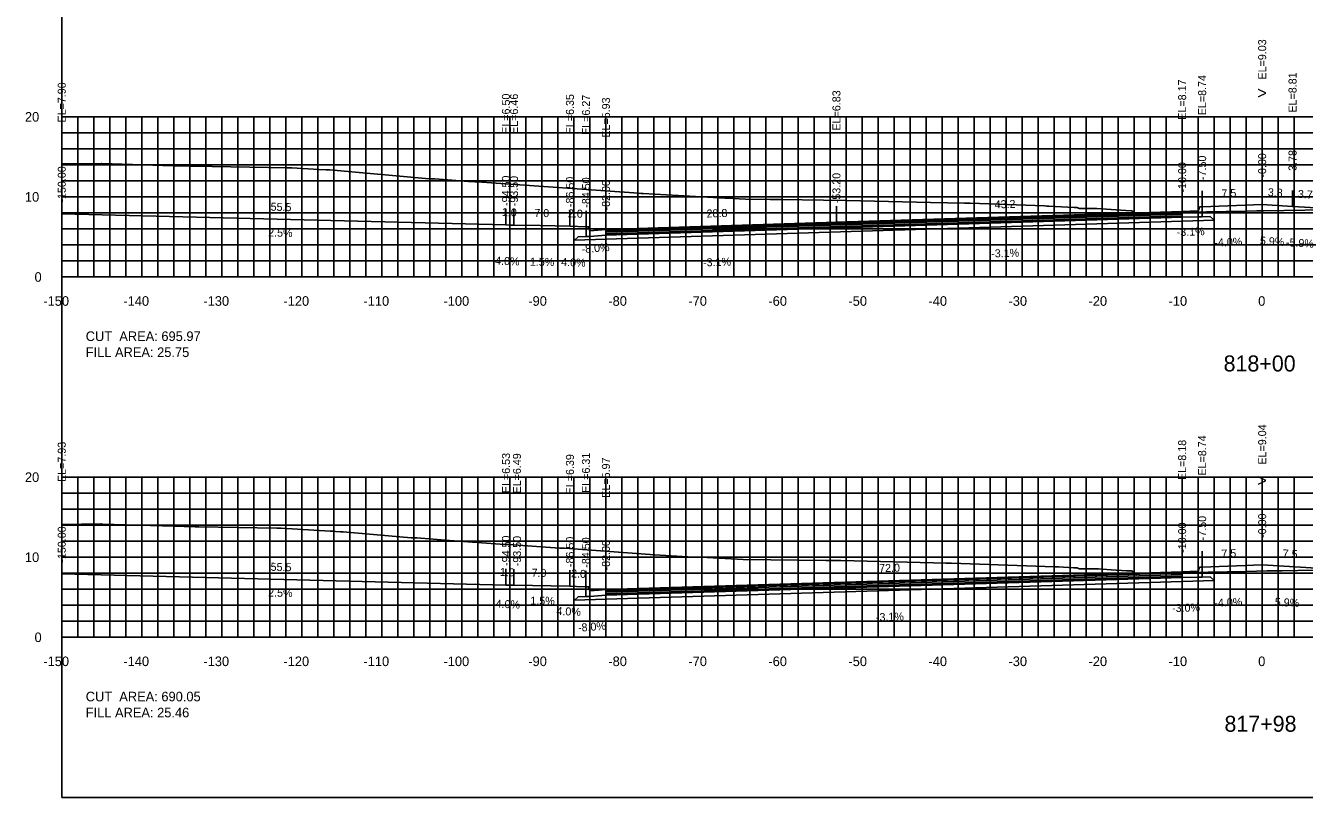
# Model space of a CAD drawing. Extents: x 1797419 to 1809236, y 248759 to 251512.
# Drawn here: x 1805536.5 to 1805696.3, y 250079.4 to 250175.8 of the extents above; entities that cross this region are included whole.
import ezdxf

# ---------------------------------------------------------------- set-up
doc = ezdxf.new("R2010")
doc.units = 0
for name, color, linetype in [('1', 7, 'Continuous'), ('10', 7, 'Continuous'), ('3', 7, 'Continuous'), ('31', 7, 'Continuous'), ('4', 7, 'Continuous'), ('60', 7, 'Continuous'), ('ANNO-TXT', 7, 'Continuous'), ('BASE', 7, 'Continuous'), ('CL-CNST', 7, 'Continuous'), ('Level 62', 7, 'Continuous'), ('LOWER BINDER', 7, 'Continuous'), ('M-ROADS', 7, 'Continuous'), ('UPPER BINDER', 7, 'Continuous'), ('WEARING', 7, 'Continuous')]:
    doc.layers.add(name, color=color, linetype=linetype)

msp = doc.modelspace()

# ---------------------------------------------------------------- linework, layer by layer
for p, q in [((1805691, 250153.47), (1805691, 250155.47)), ((1805541, 250152.33), (1805541, 250154.33)), ((1805681, 250152.6), (1805681, 250154.6)), ((1805683.5, 250153.17), (1805683.5, 250155.17)), ((1805694.79, 250153.24), (1805694.79, 250155.24)), ((1805596.5, 250150.93), (1805596.5, 250152.93)), ((1805597.51, 250150.89), (1805597.51, 250152.89)), ((1805604.5, 250150.78), (1805604.5, 250152.78)), ((1805606.51, 250150.7), (1805606.51, 250152.7)), ((1805609, 250150.36), (1805609, 250152.36)), ((1805637.8, 250151.26), (1805637.8, 250153.26)), ((1805541, 250107.36), (1805541, 250109.36)), ((1805681, 250107.61), (1805681, 250109.61)), ((1805683.5, 250108.17), (1805683.5, 250110.17)), ((1805691, 250108.47), (1805691, 250110.47)), ((1805596.51, 250105.96), (1805596.51, 250107.96)), ((1805597.51, 250105.92), (1805597.51, 250107.92)), ((1805604.5, 250105.82), (1805604.5, 250107.82)), ((1805606.5, 250105.74), (1805606.5, 250107.74)), ((1805609, 250105.4), (1805609, 250107.4))]:
    msp.add_line(p, q)
for points in [[(1805541, 250079.43), (1805841, 250079.43), (1805841, 250269.43), (1805541, 250269.43)], [(1805683.5, 250153.17), (1805683.17, 250153.17), (1805683, 250152.67), (1805681, 250152.6), (1805681, 250151.88), (1805683, 250151.95), (1805683.5, 250151.95)], [(1805609, 250150.36), (1805607, 250150.2), (1805606.83, 250150.7), (1805606.51, 250150.7), (1805606.51, 250149.48), (1805607, 250149.48), (1805609, 250149.64)], [(1805683.5, 250108.17), (1805683.17, 250108.17), (1805683, 250107.67), (1805681, 250107.61), (1805681, 250106.89), (1805683, 250106.95), (1805683.5, 250106.95)], [(1805609, 250105.4), (1805607, 250105.24), (1805606.83, 250105.74), (1805606.5, 250105.74), (1805606.5, 250104.52), (1805607, 250104.52), (1805609, 250104.68)]]:
    msp.add_lwpolyline(points, close=True)
at = {"layer": '60'}
for p, q in [((1805540.94, 250164.43), (1805541, 250164.43)), ((1805541, 250144.43), (1805541, 250164.43)), ((1805540.94, 250154.43), (1805541, 250154.43)), ((1805540.94, 250144.43), (1805541, 250144.43)), ((1805541, 250144.43), (1805841, 250144.43)), ((1805541, 250144.37), (1805541, 250144.43)), ((1805551, 250144.37), (1805551, 250144.43)), ((1805561, 250144.37), (1805561, 250144.43)), ((1805571, 250144.37), (1805571, 250144.43)), ((1805581, 250144.37), (1805581, 250144.43)), ((1805591, 250144.37), (1805591, 250144.43)), ((1805601, 250144.37), (1805601, 250144.43)), ((1805611, 250144.37), (1805611, 250144.43)), ((1805621, 250144.37), (1805621, 250144.43)), ((1805631, 250144.37), (1805631, 250144.43)), ((1805641, 250144.37), (1805641, 250144.43)), ((1805651, 250144.37), (1805651, 250144.43)), ((1805661, 250144.37), (1805661, 250144.43)), ((1805671, 250144.37), (1805671, 250144.43)), ((1805681, 250144.37), (1805681, 250144.43)), ((1805691, 250144.37), (1805691, 250144.43)), ((1805540.94, 250119.43), (1805541, 250119.43)), ((1805541, 250099.43), (1805541, 250119.43)), ((1805540.94, 250109.43), (1805541, 250109.43)), ((1805540.94, 250099.43), (1805541, 250099.43)), ((1805541, 250099.43), (1805841, 250099.43)), ((1805541, 250099.37), (1805541, 250099.43)), ((1805551, 250099.37), (1805551, 250099.43)), ((1805561, 250099.37), (1805561, 250099.43)), ((1805571, 250099.37), (1805571, 250099.43)), ((1805581, 250099.37), (1805581, 250099.43)), ((1805591, 250099.37), (1805591, 250099.43)), ((1805601, 250099.37), (1805601, 250099.43)), ((1805611, 250099.37), (1805611, 250099.43)), ((1805621, 250099.37), (1805621, 250099.43)), ((1805631, 250099.37), (1805631, 250099.43)), ((1805641, 250099.37), (1805641, 250099.43)), ((1805651, 250099.37), (1805651, 250099.43)), ((1805661, 250099.37), (1805661, 250099.43)), ((1805671, 250099.37), (1805671, 250099.43)), ((1805681, 250099.37), (1805681, 250099.43)), ((1805691, 250099.37), (1805691, 250099.43))]:
    msp.add_line(p, q, dxfattribs=at)
at = {"layer": 'BASE'}
for points in [[(1805605.06, 250149.02), (1805605.51, 250149.46), (1805606.51, 250149.48), (1805607, 250149.48), (1805609, 250149.64), (1805681, 250151.88), (1805683, 250151.95), (1805683.5, 250151.95), (1805684.5, 250151.98), (1805684.98, 250151.51), (1805681, 250151.38), (1805609, 250149.14)], [(1805605.07, 250104.06), (1805605.51, 250104.5), (1805606.5, 250104.52), (1805607, 250104.52), (1805609, 250104.68), (1805681, 250106.89), (1805683, 250106.95), (1805683.5, 250106.95), (1805684.5, 250106.98), (1805684.98, 250106.51), (1805681, 250106.39), (1805609, 250104.18)]]:
    msp.add_lwpolyline(points, close=True, dxfattribs=at)
at = {"layer": 'CL-CNST'}
for points in [[(1805541, 250152.33), (1805596.5, 250150.93), (1805597, 250150.91), (1805597.51, 250150.89), (1805600.8, 250150.84), (1805604.5, 250150.78), (1805606.51, 250150.7), (1805606.71, 250150.7), (1805606.83, 250150.7), (1805606.9, 250150.51), (1805607, 250150.2), (1805609, 250150.36), (1805637.8, 250151.26), (1805681, 250152.6), (1805683, 250152.67), (1805683.11, 250152.99), (1805683.17, 250153.17), (1805683.38, 250153.17), (1805683.5, 250153.17), (1805691, 250153.47), (1805694.79, 250153.24), (1805698.5, 250153.02)], [(1805541, 250107.36), (1805596.51, 250105.96), (1805597.51, 250105.92), (1805604.5, 250105.82), (1805605.32, 250105.79), (1805606.5, 250105.74), (1805606.63, 250105.74), (1805606.83, 250105.74), (1805607, 250105.24), (1805608.1, 250105.33), (1805609, 250105.4), (1805681, 250107.61), (1805683, 250107.67), (1805683.17, 250108.17), (1805683.5, 250108.17), (1805691, 250108.47), (1805698.5, 250108.03)]]:
    msp.add_lwpolyline(points, dxfattribs=at)
at = {"layer": 'Level 62'}
for p, q in [((1805541, 250164.43), (1805841, 250164.43)), ((1805541, 250144.43), (1805541, 250164.43)), ((1805543, 250144.43), (1805543, 250164.43)), ((1805545, 250144.43), (1805545, 250164.43)), ((1805547, 250144.43), (1805547, 250164.43)), ((1805549, 250144.43), (1805549, 250164.43)), ((1805551, 250144.43), (1805551, 250164.43)), ((1805553, 250144.43), (1805553, 250164.43)), ((1805555, 250144.43), (1805555, 250164.43)), ((1805557, 250144.43), (1805557, 250164.43)), ((1805559, 250144.43), (1805559, 250164.43)), ((1805561, 250144.43), (1805561, 250164.43)), ((1805563, 250144.43), (1805563, 250164.43)), ((1805565, 250144.43), (1805565, 250164.43)), ((1805567, 250144.43), (1805567, 250164.43)), ((1805569, 250144.43), (1805569, 250164.43)), ((1805571, 250144.43), (1805571, 250164.43)), ((1805573, 250144.43), (1805573, 250164.43)), ((1805575, 250144.43), (1805575, 250164.43)), ((1805577, 250144.43), (1805577, 250164.43)), ((1805579, 250144.43), (1805579, 250164.43)), ((1805581, 250144.43), (1805581, 250164.43)), ((1805583, 250144.43), (1805583, 250164.43)), ((1805585, 250144.43), (1805585, 250164.43)), ((1805587, 250144.43), (1805587, 250164.43)), ((1805589, 250144.43), (1805589, 250164.43)), ((1805591, 250144.43), (1805591, 250164.43)), ((1805593, 250144.43), (1805593, 250164.43)), ((1805595, 250144.43), (1805595, 250164.43)), ((1805597, 250144.43), (1805597, 250164.43)), ((1805599, 250144.43), (1805599, 250164.43)), ((1805601, 250144.43), (1805601, 250164.43)), ((1805603, 250144.43), (1805603, 250164.43)), ((1805605, 250144.43), (1805605, 250164.43)), ((1805607, 250144.43), (1805607, 250164.43)), ((1805609, 250144.43), (1805609, 250164.43)), ((1805611, 250144.43), (1805611, 250164.43)), ((1805613, 250144.43), (1805613, 250164.43)), ((1805615, 250144.43), (1805615, 250164.43)), ((1805617, 250144.43), (1805617, 250164.43)), ((1805619, 250144.43), (1805619, 250164.43)), ((1805621, 250144.43), (1805621, 250164.43)), ((1805623, 250144.43), (1805623, 250164.43)), ((1805625, 250144.43), (1805625, 250164.43)), ((1805627, 250144.43), (1805627, 250164.43)), ((1805629, 250144.43), (1805629, 250164.43)), ((1805631, 250144.43), (1805631, 250164.43)), ((1805633, 250144.43), (1805633, 250164.43)), ((1805635, 250144.43), (1805635, 250164.43)), ((1805637, 250144.43), (1805637, 250164.43)), ((1805639, 250144.43), (1805639, 250164.43)), ((1805641, 250144.43), (1805641, 250164.43)), ((1805643, 250144.43), (1805643, 250164.43)), ((1805645, 250144.43), (1805645, 250164.43)), ((1805647, 250144.43), (1805647, 250164.43)), ((1805649, 250144.43), (1805649, 250164.43)), ((1805651, 250144.43), (1805651, 250164.43)), ((1805653, 250144.43), (1805653, 250164.43)), ((1805655, 250144.43), (1805655, 250164.43)), ((1805657, 250144.43), (1805657, 250164.43)), ((1805659, 250144.43), (1805659, 250164.43)), ((1805661, 250144.43), (1805661, 250164.43)), ((1805663, 250144.43), (1805663, 250164.43)), ((1805665, 250144.43), (1805665, 250164.43)), ((1805667, 250144.43), (1805667, 250164.43)), ((1805669, 250144.43), (1805669, 250164.43)), ((1805671, 250144.43), (1805671, 250164.43)), ((1805673, 250144.43), (1805673, 250164.43)), ((1805675, 250144.43), (1805675, 250164.43)), ((1805677, 250144.43), (1805677, 250164.43)), ((1805679, 250144.43), (1805679, 250164.43)), ((1805681, 250144.43), (1805681, 250164.43)), ((1805683, 250144.43), (1805683, 250164.43)), ((1805685, 250144.43), (1805685, 250164.43)), ((1805687, 250144.43), (1805687, 250164.43)), ((1805689, 250144.43), (1805689, 250164.43)), ((1805691, 250144.43), (1805691, 250164.43)), ((1805693, 250144.43), (1805693, 250164.43)), ((1805695, 250144.43), (1805695, 250164.43)), ((1805541, 250162.43), (1805841, 250162.43)), ((1805541, 250160.43), (1805841, 250160.43)), ((1805541, 250158.43), (1805841, 250158.43)), ((1805541, 250156.43), (1805841, 250156.43)), ((1805541, 250154.43), (1805841, 250154.43)), ((1805541, 250152.43), (1805841, 250152.43)), ((1805541, 250150.43), (1805841, 250150.43)), ((1805541, 250148.43), (1805841, 250148.43)), ((1805541, 250146.43), (1805841, 250146.43)), ((1805541, 250144.43), (1805841, 250144.43)), ((1805541, 250119.43), (1805841, 250119.43)), ((1805541, 250099.43), (1805541, 250119.43)), ((1805543, 250099.43), (1805543, 250119.43)), ((1805545, 250099.43), (1805545, 250119.43)), ((1805547, 250099.43), (1805547, 250119.43)), ((1805549, 250099.43), (1805549, 250119.43)), ((1805551, 250099.43), (1805551, 250119.43)), ((1805553, 250099.43), (1805553, 250119.43)), ((1805555, 250099.43), (1805555, 250119.43)), ((1805557, 250099.43), (1805557, 250119.43)), ((1805559, 250099.43), (1805559, 250119.43)), ((1805561, 250099.43), (1805561, 250119.43)), ((1805563, 250099.43), (1805563, 250119.43)), ((1805565, 250099.43), (1805565, 250119.43)), ((1805567, 250099.43), (1805567, 250119.43)), ((1805569, 250099.43), (1805569, 250119.43)), ((1805571, 250099.43), (1805571, 250119.43)), ((1805573, 250099.43), (1805573, 250119.43)), ((1805575, 250099.43), (1805575, 250119.43)), ((1805577, 250099.43), (1805577, 250119.43)), ((1805579, 250099.43), (1805579, 250119.43)), ((1805581, 250099.43), (1805581, 250119.43)), ((1805583, 250099.43), (1805583, 250119.43)), ((1805585, 250099.43), (1805585, 250119.43)), ((1805587, 250099.43), (1805587, 250119.43)), ((1805589, 250099.43), (1805589, 250119.43)), ((1805591, 250099.43), (1805591, 250119.43)), ((1805593, 250099.43), (1805593, 250119.43)), ((1805595, 250099.43), (1805595, 250119.43)), ((1805597, 250099.43), (1805597, 250119.43)), ((1805599, 250099.43), (1805599, 250119.43)), ((1805601, 250099.43), (1805601, 250119.43)), ((1805603, 250099.43), (1805603, 250119.43)), ((1805605, 250099.43), (1805605, 250119.43)), ((1805607, 250099.43), (1805607, 250119.43)), ((1805609, 250099.43), (1805609, 250119.43)), ((1805611, 250099.43), (1805611, 250119.43)), ((1805613, 250099.43), (1805613, 250119.43)), ((1805615, 250099.43), (1805615, 250119.43)), ((1805617, 250099.43), (1805617, 250119.43)), ((1805619, 250099.43), (1805619, 250119.43)), ((1805621, 250099.43), (1805621, 250119.43)), ((1805623, 250099.43), (1805623, 250119.43)), ((1805625, 250099.43), (1805625, 250119.43)), ((1805627, 250099.43), (1805627, 250119.43)), ((1805629, 250099.43), (1805629, 250119.43)), ((1805631, 250099.43), (1805631, 250119.43)), ((1805633, 250099.43), (1805633, 250119.43)), ((1805635, 250099.43), (1805635, 250119.43)), ((1805637, 250099.43), (1805637, 250119.43)), ((1805639, 250099.43), (1805639, 250119.43)), ((1805641, 250099.43), (1805641, 250119.43)), ((1805643, 250099.43), (1805643, 250119.43)), ((1805645, 250099.43), (1805645, 250119.43)), ((1805647, 250099.43), (1805647, 250119.43)), ((1805649, 250099.43), (1805649, 250119.43)), ((1805651, 250099.43), (1805651, 250119.43)), ((1805653, 250099.43), (1805653, 250119.43)), ((1805655, 250099.43), (1805655, 250119.43)), ((1805657, 250099.43), (1805657, 250119.43)), ((1805659, 250099.43), (1805659, 250119.43)), ((1805661, 250099.43), (1805661, 250119.43)), ((1805663, 250099.43), (1805663, 250119.43)), ((1805665, 250099.43), (1805665, 250119.43)), ((1805667, 250099.43), (1805667, 250119.43)), ((1805669, 250099.43), (1805669, 250119.43)), ((1805671, 250099.43), (1805671, 250119.43)), ((1805673, 250099.43), (1805673, 250119.43)), ((1805675, 250099.43), (1805675, 250119.43)), ((1805677, 250099.43), (1805677, 250119.43)), ((1805679, 250099.43), (1805679, 250119.43)), ((1805681, 250099.43), (1805681, 250119.43)), ((1805683, 250099.43), (1805683, 250119.43)), ((1805685, 250099.43), (1805685, 250119.43)), ((1805687, 250099.43), (1805687, 250119.43)), ((1805689, 250099.43), (1805689, 250119.43)), ((1805691, 250099.43), (1805691, 250119.43)), ((1805693, 250099.43), (1805693, 250119.43)), ((1805695, 250099.43), (1805695, 250119.43)), ((1805541, 250117.43), (1805841, 250117.43)), ((1805541, 250115.43), (1805841, 250115.43)), ((1805541, 250113.43), (1805841, 250113.43)), ((1805541, 250111.43), (1805841, 250111.43)), ((1805541, 250109.43), (1805841, 250109.43)), ((1805541, 250107.43), (1805841, 250107.43)), ((1805541, 250105.43), (1805841, 250105.43)), ((1805541, 250103.43), (1805841, 250103.43)), ((1805541, 250101.43), (1805841, 250101.43)), ((1805541, 250099.43), (1805841, 250099.43))]:
    msp.add_line(p, q, dxfattribs=at)
at = {"layer": 'LOWER BINDER'}
for points in [[(1805609, 250149.83), (1805609, 250150.02), (1805681, 250152.26), (1805681, 250152.07)], [(1805609, 250149.64), (1805609, 250149.83), (1805681, 250152.07), (1805681, 250151.88)], [(1805609, 250104.87), (1805609, 250105.06), (1805681, 250107.27), (1805681, 250107.08)], [(1805609, 250104.68), (1805609, 250104.87), (1805681, 250107.08), (1805681, 250106.89)]]:
    msp.add_lwpolyline(points, close=True, dxfattribs=at)
at = {"layer": 'M-ROADS'}
for points in [[(1805541, 250158.54), (1805545.94, 250158.61), (1805546.03, 250158.61), (1805554.94, 250158.32), (1805556.98, 250158.27), (1805557.05, 250158.27), (1805557.46, 250158.26), (1805569.17, 250158.05), (1805569.67, 250158.05), (1805569.74, 250158.05), (1805572.44, 250157.89), (1805572.99, 250157.86), (1805573.14, 250157.86), (1805574.03, 250157.81), (1805574.49, 250157.79), (1805586.91, 250156.7), (1805587.52, 250156.68), (1805587.64, 250156.67), (1805589.2, 250156.55), (1805591.84, 250156.37), (1805592.62, 250156.33), (1805592.91, 250156.32), (1805604.8, 250155.47), (1805605.06, 250155.46), (1805605.4, 250155.45), (1805613.06, 250154.88), (1805613.4, 250154.87), (1805613.65, 250154.86), (1805623.87, 250154.26), (1805624.09, 250154.26), (1805624.85, 250154.23), (1805626.44, 250154.15), (1805629.5, 250154.12), (1805630.42, 250154.11), (1805630.88, 250154.1), (1805636.18, 250154.03), (1805638.99, 250153.99), (1805639.07, 250153.99), (1805649.57, 250153.74), (1805653.8, 250153.64), (1805654.06, 250153.64), (1805654.5, 250153.63), (1805663.81, 250153.3), (1805664.09, 250153.29), (1805664.35, 250153.29), (1805667.52, 250153.09), (1805667.58, 250153.09), (1805667.86, 250153.09), (1805668.18, 250152.98), (1805668.2, 250152.98), (1805670.36, 250152.97), (1805672.12, 250152.84), (1805673.98, 250152.74), (1805674.72, 250152.71), (1805675.11, 250152.39), (1805675.25, 250152.26), (1805675.49, 250152.35), (1805675.5, 250152.36), (1805675.53, 250152.39), (1805675.53, 250152.4), (1805676.62, 250152.42), (1805688.95, 250152.66), (1805690.34, 250152.69), (1805691.16, 250152.71), (1805701.54, 250152.87)], [(1805541, 250113.5), (1805545.92, 250113.58), (1805546.05, 250113.57), (1805553.59, 250113.33), (1805557.67, 250113.23), (1805557.81, 250113.23), (1805558.15, 250113.22), (1805567.87, 250113.04), (1805568.28, 250113.04), (1805568.43, 250113.04), (1805574.52, 250112.68), (1805574.91, 250112.67), (1805575.22, 250112.65), (1805575.83, 250112.62), (1805576.15, 250112.61), (1805584.65, 250111.86), (1805585.06, 250111.84), (1805585.38, 250111.83), (1805589.44, 250111.52), (1805596.38, 250111.03), (1805596.79, 250111.01), (1805597.45, 250110.98), (1805603.24, 250110.57), (1805603.37, 250110.57), (1805603.84, 250110.55), (1805614.52, 250109.75), (1805614.99, 250109.73), (1805615.11, 250109.73), (1805619.91, 250109.45), (1805620.5, 250109.43), (1805620.89, 250109.42), (1805626.16, 250109.14), (1805636.48, 250109.03), (1805636.57, 250109.03), (1805637.51, 250109.02), (1805637.61, 250109.02), (1805637.69, 250109.02), (1805638.35, 250109), (1805649.92, 250108.73), (1805651.47, 250108.69), (1805651.57, 250108.69), (1805652.17, 250108.68), (1805665.03, 250108.23), (1805665.41, 250108.22), (1805665.57, 250108.22), (1805667.48, 250108.09), (1805667.52, 250108.09), (1805667.82, 250108.09), (1805668.18, 250107.98), (1805668.2, 250107.98), (1805670.55, 250107.96), (1805672.12, 250107.85), (1805674.06, 250107.74), (1805674.71, 250107.72), (1805675.13, 250107.39), (1805675.25, 250107.27), (1805675.5, 250107.36), (1805675.5, 250107.37), (1805684.25, 250107.55), (1805688.95, 250107.65), (1805691.62, 250107.71), (1805693.03, 250107.74), (1805693.5, 250107.75), (1805699.4, 250107.84)]]:
    msp.add_lwpolyline(points, dxfattribs=at)
at = {"layer": 'UPPER BINDER'}
for points in [[(1805681, 250152.45), (1805609, 250150.21), (1805609, 250150.02), (1805681, 250152.26)], [(1805681, 250107.46), (1805609, 250105.25), (1805609, 250105.06), (1805681, 250107.27)]]:
    msp.add_lwpolyline(points, close=True, dxfattribs=at)
at = {"layer": 'WEARING'}
for points in [[(1805681, 250152.6), (1805609, 250150.36), (1805609, 250150.21), (1805681, 250152.45)], [(1805681, 250107.61), (1805609, 250105.4), (1805609, 250105.25), (1805681, 250107.46)]]:
    msp.add_lwpolyline(points, close=True, dxfattribs=at)

# ---------------------------------------------------------------- texts
at = {"layer": '1'}
for s, p in [('818+00', (1805686.18, 250132.63)), ('817+98', (1805686.29, 250087.63))]:
    msp.add_text(s, height=2, dxfattribs=at).set_placement(p)
at = {"layer": '10'}
for s, p in [('-150', (1805538.7, 250140.83)), ('-140', (1805548.7, 250140.83)), ('-130', (1805558.7, 250140.83)), ('-120', (1805568.7, 250140.83)), ('-110', (1805578.7, 250140.83)), ('-100', (1805588.7, 250140.83)), ('-90', (1805599.3, 250140.83)), ('-80', (1805609.3, 250140.83)), ('-70', (1805619.3, 250140.83)), ('-60', (1805629.3, 250140.83)), ('-50', (1805639.3, 250140.83)), ('-40', (1805649.3, 250140.83)), ('-30', (1805659.3, 250140.83)), ('-20', (1805669.3, 250140.83)), ('-10', (1805679.3, 250140.83)), ('0', (1805690.5, 250140.83)), ('-150', (1805538.7, 250095.83)), ('-140', (1805548.7, 250095.83)), ('-130', (1805558.7, 250095.83)), ('-120', (1805568.7, 250095.83)), ('-110', (1805578.7, 250095.83)), ('-100', (1805588.7, 250095.83)), ('-90', (1805599.3, 250095.83)), ('-80', (1805609.3, 250095.83)), ('-70', (1805619.3, 250095.83)), ('-60', (1805629.3, 250095.83)), ('-50', (1805639.3, 250095.83)), ('-40', (1805649.3, 250095.83)), ('-30', (1805659.3, 250095.83)), ('-20', (1805669.3, 250095.83)), ('-10', (1805679.3, 250095.83)), ('0', (1805690.5, 250095.83))]:
    msp.add_text(s, height=1.2, dxfattribs=at).set_placement(p)
at = {"layer": '3'}
for s, p in [('EL=9.03', (1805691.5, 250169.09)), ('EL=8.81', (1805695.29, 250164.96)), ('EL=7.90', (1805541.5, 250163.72)), ('EL=8.17', (1805681.5, 250164.07)), ('EL=8.74', (1805684, 250164.63)), ('EL=6.50', (1805597, 250162.31)), ('EL=6.46', (1805598.01, 250162.3)), ('EL=6.35', (1805605, 250162.25)), ('EL=6.27', (1805607.01, 250162.17)), ('EL=5.93', (1805609.5, 250161.83)), ('EL=6.83', (1805638.3, 250162.72)), ('3.78', (1805695.29, 250157.68)), ('-10.00', (1805681.5, 250154.98)), ('-7.50', (1805684, 250156.54)), ('-0.00', (1805691.5, 250156.84)), ('-150.00', (1805541.5, 250153.72)), ('-94.50', (1805597, 250153.3)), ('-93.50', (1805598.01, 250153.26)), ('-53.20', (1805638.3, 250153.64)), ('-86.50', (1805605, 250153.16)), ('-84.50', (1805607.01, 250153.08)), ('-82.00', (1805609.5, 250152.74)), ('EL=9.04', (1805691.5, 250121)), ('EL=7.93', (1805541.5, 250118.82)), ('EL=8.18', (1805681.5, 250119.07)), ('EL=8.74', (1805684, 250119.63)), ('EL=6.53', (1805597.01, 250117.43)), ('EL=6.49', (1805598.38, 250117.39)), ('EL=6.39', (1805605, 250117.28)), ('EL=6.31', (1805607, 250117.46)), ('EL=5.97', (1805609.5, 250116.86)), ('-7.50', (1805684, 250111.54)), ('-0.00', (1805691.5, 250111.84)), ('-150.00', (1805541.5, 250108.75)), ('-10.00', (1805681.5, 250109.98)), ('-94.50', (1805597.01, 250108.34)), ('-93.50', (1805598.39, 250108.3)), ('-86.50', (1805605, 250108.2)), ('-84.50', (1805607, 250108.12)), ('-82.00', (1805609.5, 250107.78))]:
    msp.add_text(s, height=1, rotation=90, dxfattribs=at).set_placement(p)
at = {"layer": '31'}
for s, p in [('20', (1805536.4, 250163.83)), ('10', (1805536.4, 250153.83)), ('0', (1805537.6, 250143.83)), ('20', (1805536.4, 250118.83)), ('10', (1805536.4, 250108.83)), ('0', (1805537.6, 250098.83))]:
    msp.add_text(s, height=1.2, dxfattribs=at).set_placement(p)
at = {"layer": '4'}
for s, rotation, p in [('7.5', 2.2908, (1805685.93, 250154.36)), ('3.8', 356.6121, (1805691.68, 250154.53)), ('43.2', 1.7836, (1805657.59, 250152.98)), ('3.7', 356.6121, (1805695.43, 250154.31)), ('55.5', 358.4206, (1805567.09, 250152.71)), ('1.0', 357.7106, (1805595.98, 250152.05)), ('7.0', 359.1406, (1805600.05, 250151.93)), ('2.0', 357.7098, (1805604.23, 250151.89)), ('28.8', 1.7836, (1805621.59, 250151.85)), ('-3.1%', 1.7836, (1805680.33, 250149.53)), ('2.5%', 358.4206, (1805566.78, 250149.5)), ('-4.0%', 2.2908, (1805685.04, 250148.22)), ('5.9%', 356.6121, (1805690.69, 250148.48)), ('-5.9%', 356.6121, (1805693.94, 250148.28)), ('-8.0%', 4.5731, (1805606, 250147.4)), ('-3.1%', 1.7836, (1805657.15, 250146.86)), ('4.0%', 357.7106, (1805595.14, 250145.98)), ('1.5%', 359.1406, (1805599.49, 250145.84)), ('4.0%', 357.7098, (1805603.39, 250145.82)), ('-3.1%', 1.7836, (1805621.15, 250145.74)), ('7.5', 2.2905, (1805685.92, 250109.37)), ('7.5', 356.6274, (1805693.53, 250109.42)), ('55.5', 358.4206, (1805567.09, 250107.74)), ('1.0', 357.7086, (1805595.73, 250107.1)), ('7.0', 359.1406, (1805599.7, 250106.99)), ('2.0', 357.7095, (1805604.63, 250106.91)), ('72.0', 1.7565, (1805643.15, 250107.55)), ('2.5%', 358.4206, (1805566.78, 250104.53)), ('1.5%', 359.1406, (1805599.55, 250103.52)), ('-4.0%', 2.2905, (1805685.04, 250103.23)), ('5.9%', 356.6274, (1805692.55, 250103.37)), ('4.0%', 357.7086, (1805595.2, 250103.13)), ('4.0%', 357.7095, (1805602.8, 250102.22)), ('-3.0%', 1.7463, (1805679.75, 250102.57)), ('-8.0%', 4.5738, (1805605.55, 250100.11)), ('-3.1%', 1.7565, (1805642.75, 250101.43))]:
    msp.add_text(s, height=1, rotation=rotation, dxfattribs=at).set_placement(p)
at = {"layer": '60'}
for s, height, p in [('>', 1.5, (1805690.39, 250166.68)), ('-', 0.0001, (1805541, 250144.43)), ('>', 1.5, (1805690.39, 250118.29)), ('-', 0.0001, (1805541, 250099.43))]:
    msp.add_text(s, height=height, dxfattribs=at).set_placement(p)
at = {"layer": 'ANNO-TXT'}
for s, p in [('CUT  AREA: 695.97', (1805544, 250136.43)), ('FILL AREA: 25.75', (1805544, 250134.43)), ('CUT  AREA: 690.05', (1805544, 250091.43)), ('FILL AREA: 25.46', (1805544, 250089.43))]:
    msp.add_text(s, height=1.2, dxfattribs=at).set_placement(p)

doc.saveas('drawing.dxf')
